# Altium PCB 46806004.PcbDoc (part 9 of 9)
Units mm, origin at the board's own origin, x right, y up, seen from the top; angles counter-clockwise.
Board outline 130 x 105 mm, 8 copper layers (Top Layer, P1-GND, L1-Signal, L2-Signal, L3-Signal, L4-Signal, P2-GND, Bottom Layer), stack 1.63 mm thick; 796 components, 496 nets, 2808 pads, 1195 vias.
Unrouted connection lines stored in the file: 1.
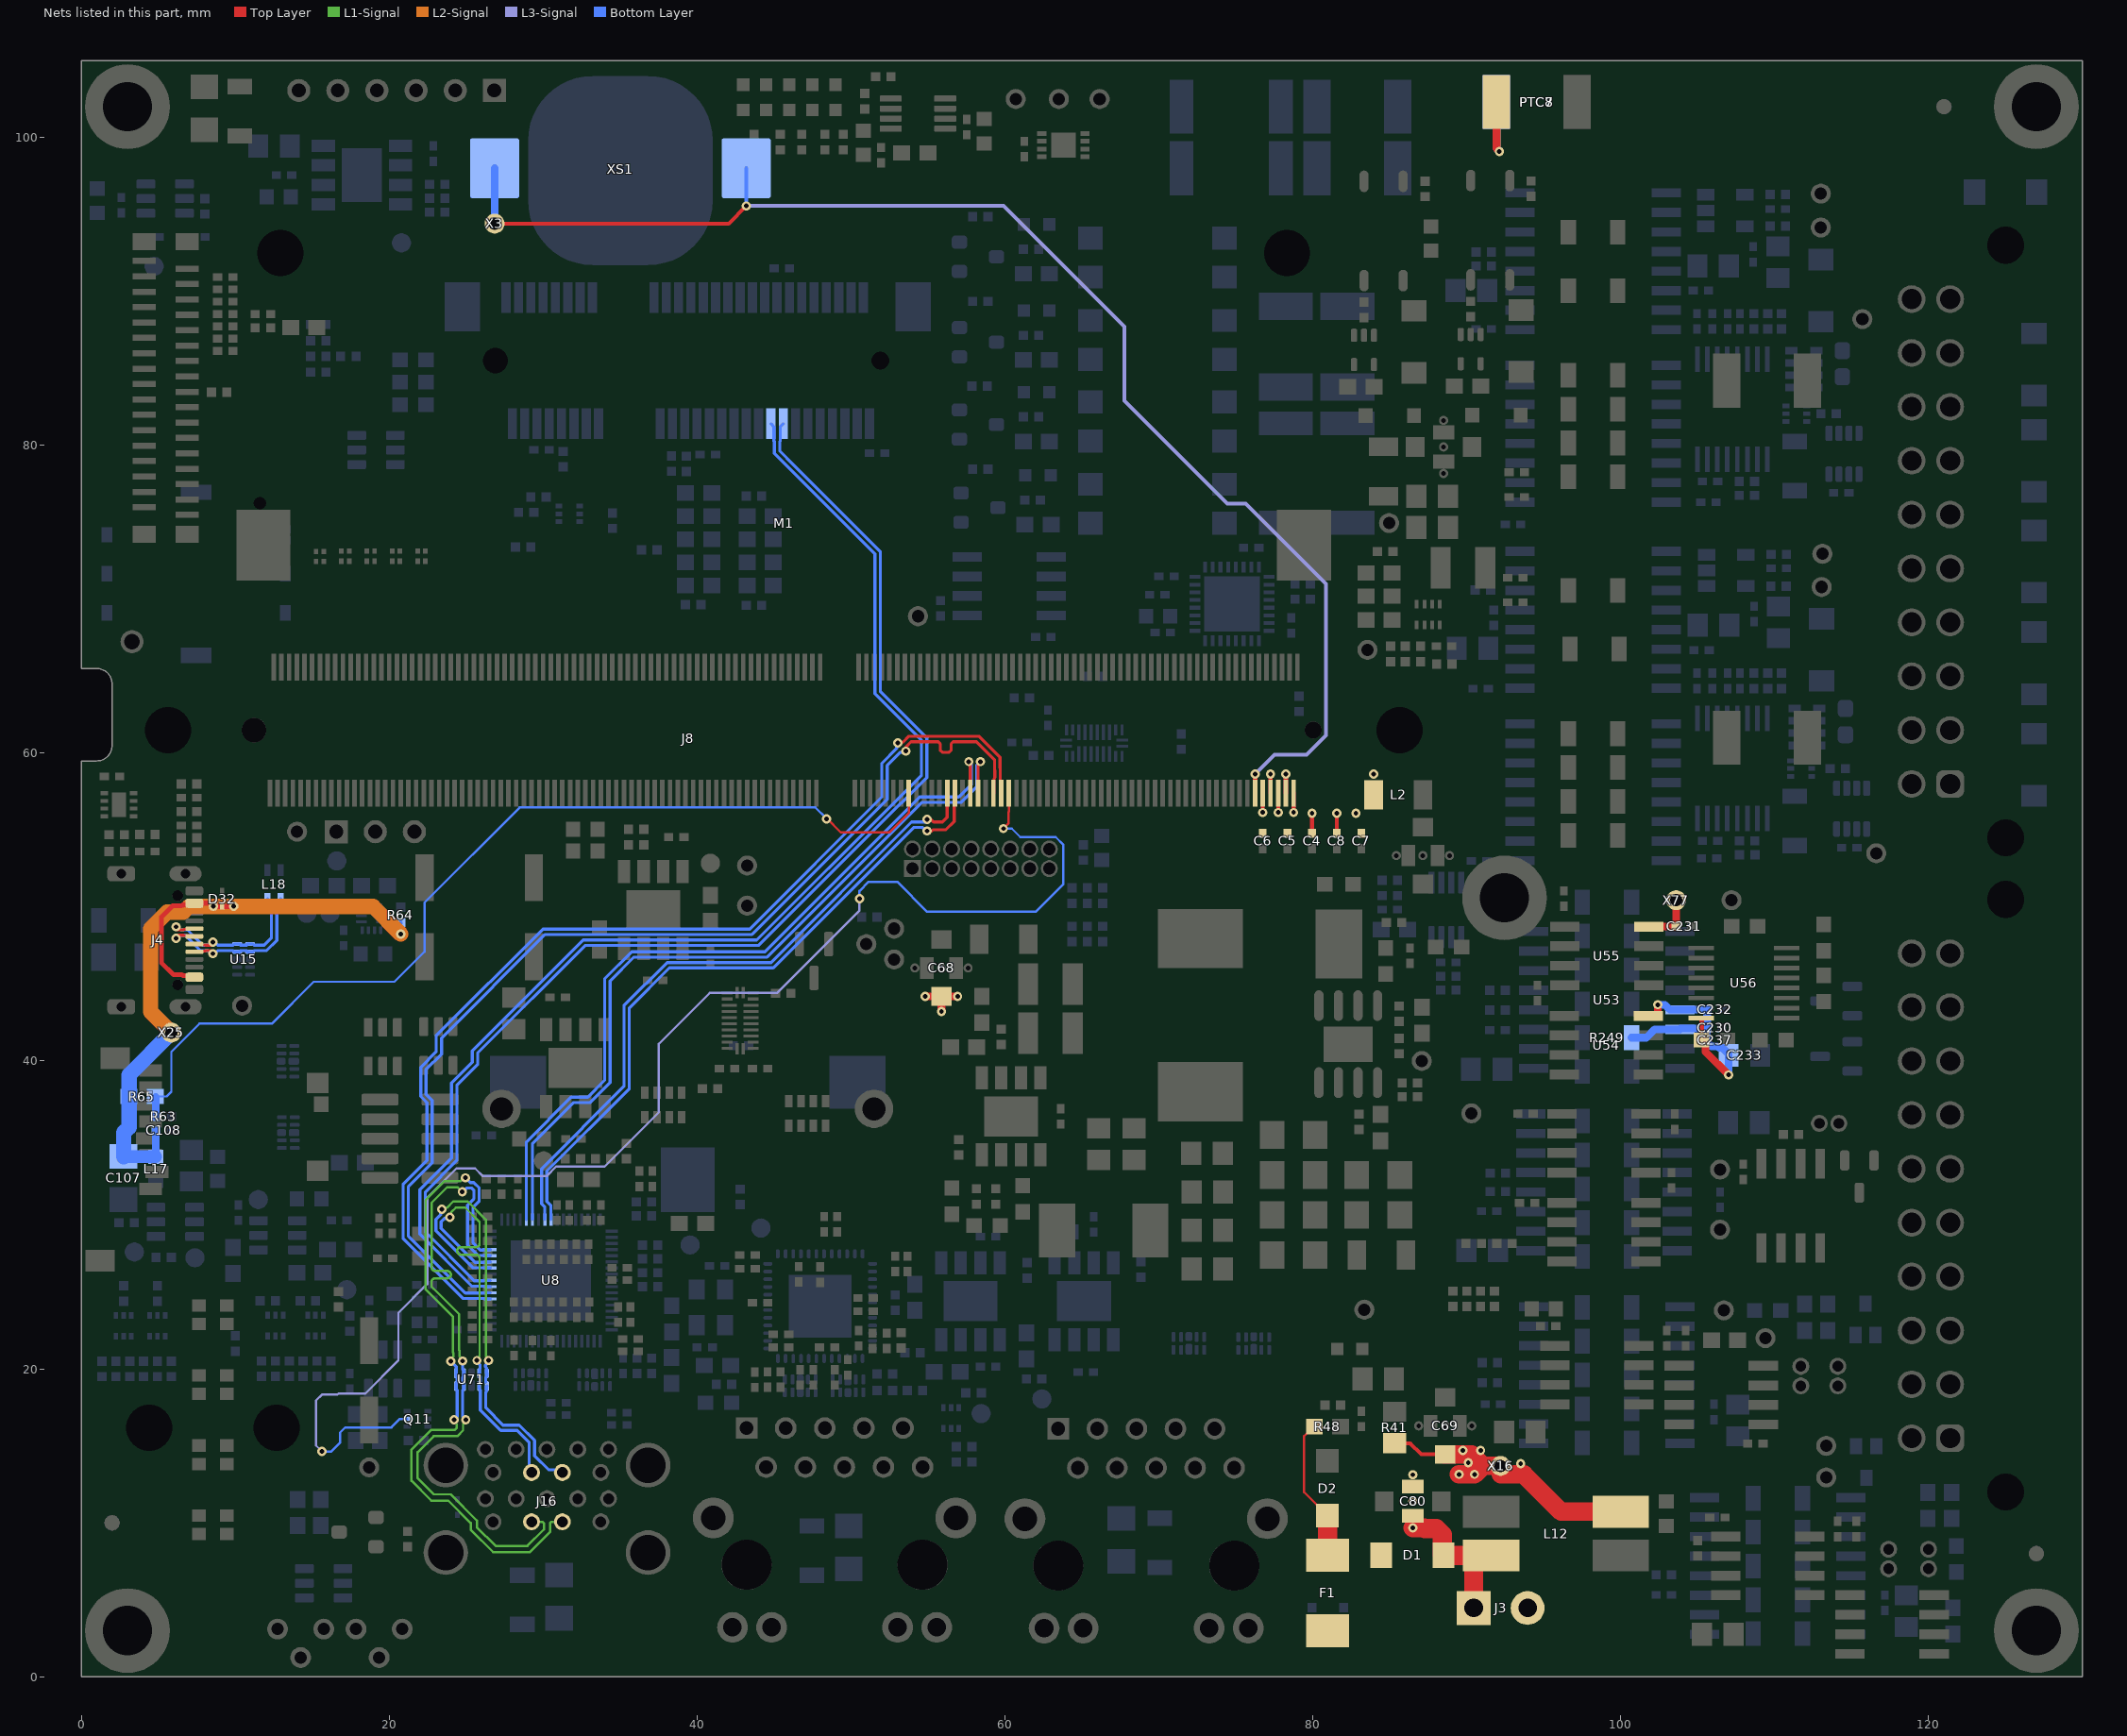
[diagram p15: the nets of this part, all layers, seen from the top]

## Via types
v1: diameter 0.6, hole 0.3, Top Layer to Bottom Layer, tented both sides, 1130 vias
v2: diameter 0.6, hole 0.3, Top Layer to Bottom Layer, 53 vias
v3: diameter 0.3, hole 0.3, Top Layer to Bottom Layer, 12 vias

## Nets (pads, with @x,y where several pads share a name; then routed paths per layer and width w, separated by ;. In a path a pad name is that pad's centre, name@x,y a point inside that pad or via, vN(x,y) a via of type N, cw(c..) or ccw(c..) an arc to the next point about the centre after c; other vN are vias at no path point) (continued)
USB1_VBUS: M1.159 R63.2 R65.2 | length 64
  Top Layer w0.15: v1(48.405,55.722) 48.422,55.722 48.45,55.75 49.35,54.85 52.5,54.85 53.75,56.1 M1.159@53.75,57.4
  Bottom Layer w0.15: R65.2@4.85,37.65 R65.2@4.8,37.7 5.55,37.7 5.85,38 5.85,40.6 7.675,42.425 12.375,42.425 15.1,45.15 20.341,45.15 22.3,47.109 22.3,50.299 28.476,56.475 34.408,56.475 35.092,56.475 47.694,56.475 48.405,55.764 v1(48.405,55.722)
  Bottom Layer w0.5: R63.2@4.85,36.4 R65.2@4.85,37.65
USB2_EN: M1.185 Q11.2 | length 92.5
  Top Layer w0.15: v1(59.9,55.1) 60.225,55.425 60.225,56.167 60.25,56.192 M1.185@60.25,57.4
  L3-Signal w0.15: v1(15.638,14.638) 15.25,15.026 15.25,17.942 15.633,18.325 16.633,18.325 16.708,18.4 18.45,18.4 20.6,20.55 20.6,23.642 22.475,25.517 22.475,31.125 24.371,33.021 25.586,33.021 26.083,32.525 30.225,32.525 30.85,33.15 34.001,33.15 37.522,36.671 37.522,41.122 40.825,44.425 45.187,44.425 50.55,49.788 v1(50.55,50.55)
  Bottom Layer w0.15: v1(15.638,14.638) 16.238,14.638 16.8,15.2 16.8,15.85 17.15,16.2 20.15,16.2 20.7,16.75 Q11.2@21.175,16.75 ; v1(50.55,50.55) 50.55,51.05 51.15,51.65 53,51.65 54.95,49.7 62,49.7 63.8,51.5 63.8,54.05 63.3,54.55 61,54.55 60.45,55.1 v1(59.9,55.1)
USB2_N: M1.181 U8.58 | length 70.1
  Top Layer w0.2: v1(53.566,60.134) 53.566,60.416 53.9,60.75 54.849,60.75 55.657,60.75 55.798,60.608 55.798,60.199 55.94,60.057 56.365,60.057 56.506,60.199 56.506,60.608 56.648,60.75 58.155,60.75 59.325,59.58 59.325,58.903 59.35,58.878 59.35,58.422 59.3,58.372 59.3,57.45 M1.181@59.25,57.4
  Bottom Layer w0.2: U8.58@26.564,24.947 26.262,24.947 26.237,24.922 24.948,24.922 21.25,28.621 21.25,31.85 22.8,33.4 22.8,37.445 22.4,37.845 22.4,39.45 23.4,40.45 23.4,41.488 30.132,48.22 43.57,48.22 52.35,57 52.35,59.2 53.207,60.057 53.49,60.057 v1(53.566,60.134)
USB2_P: M1.183 U8.57 | length 70.7
  Top Layer w0.2: v1(53.036,60.664) 53.07,60.697 53.353,60.697 53.755,61.1 58.3,61.1 59.675,59.725 59.675,59.048 59.7,59.023 59.7,58.399 59.7,57.45 M1.183@59.75,57.4
  Bottom Layer w0.2: U8.57@26.564,24.547 26.262,24.547 26.237,24.572 24.803,24.572 20.9,28.476 20.9,31.995 22.45,33.545 22.45,37.3 22.255,37.495 22.05,37.7 22.05,39.595 23.05,40.595 23.05,41.633 29.987,48.57 37.405,48.57 42.927,48.57 43.425,48.57 52,57.145 52,59.345 52.96,60.305 52.96,60.587 v1(53.036,60.664)
USB_1_N: J4.A7 J4.B7 L18.4 U15.5 U15.6 | length 12.6
  Top Layer w0.2: v1(6.15,48.725) 6.15,48.642 6.267,48.525 6.626,48.525 6.651,48.55 7.3,48.55 J4.B7@7.35,48.6 ; J4.A7@7.35,47.6 7.4,47.55 8.049,47.55 8.074,47.525 8.433,47.525 8.55,47.642 v1(8.55,47.725)
  Bottom Layer w0.2: v1(6.15,48.725) 6.258,48.725 6.458,48.525 6.895,48.525 7.895,47.525 8.242,47.525 8.442,47.725 v1(8.55,47.725) 8.658,47.725 8.858,47.525 9.183,47.525 9.866,47.525 9.941,47.6 U15.5@10.128,47.6 10.316,47.6 10.341,47.575 10.341,47.534 10.35,47.525 10.741,47.525 10.75,47.534 10.75,47.575 10.775,47.6 U15.6@10.962,47.6 11.15,47.6 11.225,47.525 11.889,47.525 12.35,47.986 12.35,50.158 12.233,50.275 12.2,50.275 12.1,50.375 L18.4@12.1,50.55
USB_1_P: J4.A6 J4.B6 L18.1 U15.4 U15.7 | length 13.2
  Top Layer w0.2: v1(6.15,47.975) 6.15,48.058 6.267,48.175 6.626,48.175 6.651,48.15 7.3,48.15 J4.A6@7.35,48.1 ; J4.B6@7.35,47.1 7.4,47.15 8.049,47.15 8.074,47.175 8.433,47.175 8.55,47.058 v1(8.55,46.975)
  Bottom Layer w0.2: v1(6.15,47.975) 6.258,47.975 6.458,48.175 6.75,48.175 7.75,47.175 8.242,47.175 8.442,46.975 v1(8.55,46.975) 8.658,46.975 8.858,47.175 9.328,47.175 9.866,47.175 9.941,47.1 U15.4@10.128,47.1 10.316,47.1 10.341,47.125 10.341,47.166 10.35,47.175 10.741,47.175 10.75,47.166 10.75,47.125 10.775,47.1 U15.7@10.962,47.1 11.15,47.1 11.225,47.175 12.034,47.175 12.7,47.841 12.7,50.158 12.817,50.275 12.85,50.275 12.95,50.375 L18.1@12.95,50.55
USB_1_VBUS: C107.2 C108.2 D32.1 J4.A4/B9 J4.B4/A9 L17.2 R64.1 R65.1 X25.1 | length 49.5
  Top Layer w0.3: J4.B4/A9@7.35,45.45 7.261,45.539 6.615,45.539 6.544,45.61 5.99,45.61 5.2,46.4 5.2,49.35 5.94,50.09 6.544,50.09 6.615,50.161 7.261,50.161 J4.A4/B9@7.35,50.25
  Top Layer w0.35: J4.A4/B9@7.35,50.25 8.38,50.25 8.593,50.037 D32.1@9.15,50.037 9.157,50.043 9.893,50.043 v1(9.9,50.05)
  L2-Signal w1: X25.1@5.85,41.85 4.5,43.2 4.5,48.6 5.575,49.675 6.624,49.675 6.999,50.05 v1(9.9,50.05) 18.953,50.05 v1(20.75,48.253)
  Bottom Layer w0.25: v1(20.75,48.253) R64.1@20.75,49
  Bottom Layer w0.5: C107.2@2.75,33.8 C107.2@2.76,33.79 ; L17.2@4.85,33.79 C108.2@4.85,35.5
  Bottom Layer w0.8: C107.2@2.76,33.79 L17.2@4.85,33.79
  Bottom Layer w1: C107.2@2.75,33.8 2.75,35.35 3.1,35.7 R65.1@3.1,37.7 3.1,39.1 X25.1@5.85,41.85
  other v1: 8.587,50.057
USB_2_SSRX_N: M1.175 U8.5 | length 51.1
  Top Layer w0.2: v1(57.65,59.45) 57.75,59.35 M1.175@57.75,57.4
  Bottom Layer w0.2: U8.5@28.911,29.695 28.911,34.745 31.817,37.65 32.9,37.65 34,38.75 34,45.345 35.755,47.1 44.405,47.1 54.455,57.15 57,57.15 57.829,57.979 57.829,59.271 v1(57.65,59.45)
USB_2_SSRX_P: M1.177 U8.6 | length 51.1
  Top Layer w0.2: M1.177@58.25,57.4 58.25,59.3 v1(58.4,59.45)
  Bottom Layer w0.2: U8.6@29.311,29.695 29.311,34.65 31.962,37.3 33.045,37.3 34.35,38.605 34.35,45.2 35.9,46.75 44.55,46.75 54.6,56.8 57.145,56.8 58.179,57.834 58.179,59.229 v1(58.4,59.45)
USB_2_SSTX_N: M1.169 U8.8 | length 44.1
  Top Layer w0.2: v1(54.95,55.7) 54.95,55.65 55.24,55.65 55.365,55.525 55.95,55.525 56.25,55.825 56.25,56.525 M1.169@56.25,57.4
  Bottom Layer w0.2: U8.8@30.111,29.695 30.111,30.511 29.9,30.723 29.9,33 35.25,38.35 35.25,43.595 38.055,46.4 44.805,46.4 53.93,55.525 54.95,55.525 54.95,55.65 v1(54.95,55.7)
USB_2_SSTX_P: M1.171 U8.9 | length 44.3
  Top Layer w0.2: v1(54.95,54.95) 55.24,54.95 55.315,55.025 56.157,55.025 56.7,55.568 56.7,56.575 56.75,56.625 M1.171@56.75,57.4
  Bottom Layer w0.2: U8.9@30.511,29.695 30.511,30.606 30.25,30.868 30.25,32.855 35.6,38.205 35.6,43.45 38.2,46.05 44.95,46.05 54.075,55.175 54.647,55.175 54.722,55.1 54.85,55.1 54.95,55 v1(54.95,54.95)
USBH2_N: J16.U2 U8.63 U71.2 U71.9 | length 28.9
  L1-Signal w0.15: v1(23.95,29.85) 24.036,29.936 24.036,30.184 24.331,30.478 24.937,30.478 25.875,29.541 25.875,28.702 25.875,28.147 cw(c25.635,28.147) 25.635,27.907 24.658,27.907 ccw(c24.658,27.667) 24.418,27.667 ccw(c24.658,27.667) 24.658,27.426 25.635,27.426 cw(c25.635,27.186) 25.875,27.186 25.875,26.143 25.875,23.312 25.875,20.847 25.7,20.672 v1(25.7,20.55)
  Bottom Layer w0.2: v1(23.95,29.85) 23.873,29.773 23.591,29.773 23.383,29.566 23.383,29.117 25.578,26.922 26.237,26.922 26.262,26.947 U8.63@26.564,26.947 ; v1(25.7,20.55) 25.7,20.479 25.9,20.279 25.9,20.005 25.875,19.98 25.875,19.742 U71.9@25.85,19.717 25.85,19.529 25.875,19.504 25.916,19.504 25.925,19.496 U71.2@25.925,19.133 ; U71.2@25.85,18.883 25.85,18.695 25.925,18.621 25.925,17.325 27.25,16 28.305,16 29.1,15.205 29.1,13.419 J16.U2@29.25,13.269 J16.U2@29.4,13.419
USBH2_P: J16.U3 U8.62 U71.1 U71.10 | length 29.2
  L1-Signal w0.15: v1(23.42,30.38) 23.506,30.466 23.753,30.466 24.165,30.878 25.103,30.878 26.275,29.706 26.275,23.146 26.275,20.847 26.45,20.672 v1(26.45,20.55)
  Bottom Layer w0.2: v1(23.42,30.38) 23.343,30.304 23.343,30.021 23.033,29.711 23.033,28.972 25.433,26.572 26.237,26.572 26.262,26.547 U8.62@26.564,26.547 ; U71.1@26.275,19.133 26.275,19.454 26.35,19.529 U71.10@26.35,19.717 26.325,19.742 26.325,20.067 26.25,20.142 26.25,20.242 26.45,20.442 v1(26.45,20.55) ; U71.1@26.35,18.883 26.325,18.858 26.325,18.533 26.275,18.483 26.275,17.47 27.395,16.35 28.45,16.35 29.45,15.35 29.45,14.35 30.35,13.45 31.069,13.45 J16.U3@31.25,13.269
USBH3_N: J16.L2 U8.64 U71.4 U71.7 | length 44.2
  L1-Signal w0.15: v1(24.75,31.508) 24.734,31.508 24.438,31.805 23.77,31.805 22.75,30.784 22.75,27.149 22.75,26.603 ccw(c22.99,26.603) 22.99,26.363 23.769,26.363 cw(c23.769,26.123) 24.009,26.123 cw(c23.769,26.123) 23.769,25.883 22.99,25.883 ccw(c22.99,25.643) 22.75,25.643 22.75,25.35 22.892,25.208 24.55,23.55 24.55,21.223 24.582,21.191 24.582,20.818 24.764,20.636 v1(24.764,20.514) ; v1(24.975,16.7) 24.975,16.578 24.8,16.403 24.8,16.009 24.422,15.631 22.891,15.631 21.85,14.59 21.85,12.9 22.9,11.85 24,11.85 25.7,10.15 25.7,9.716 26.916,8.5 28.983,8.5 30.05,9.567 30.05,9.981 29.962,10.069 J16.L2@29.25,10.069
  Bottom Layer w0.2: v1(24.75,31.508) 24.818,31.508 25.068,31.757 25.35,31.757 25.5,31.607 25.5,31.045 25.1,30.645 25.1,28.047 25.555,27.592 25.775,27.372 26.237,27.372 26.262,27.347 U8.64@26.564,27.347 ; v1(24.764,20.514) 24.764,19.991 24.85,19.904 U71.7@24.85,19.717 24.85,19.529 24.775,19.454 24.775,19.104 24.784,19.096 24.825,19.096 24.85,19.071 U71.4@24.85,18.883 24.85,18.695 24.775,18.62 24.775,16.9 v1(24.975,16.7)
USBH3_P: J16.L3 U8.65 U71.5 U71.6 | length 44.1
  L1-Signal w0.15: v1(24,20.5) 24,20.622 24.182,20.804 24.182,21.025 24.15,21.057 24.15,23.384 22.35,25.184 22.35,30.95 23.605,32.205 24.637,32.205 24.847,32.415 v1(24.95,32.415) ; v1(24.225,16.7) 24.225,16.578 24.4,16.403 24.4,16.175 24.256,16.031 22.726,16.031 21.45,14.755 21.45,12.734 22.734,11.45 23.834,11.45 25.3,9.984 25.3,9.55 26.75,8.1 29.148,8.1 30.45,9.402 30.45,9.981 30.538,10.069 J16.L3@31.25,10.069
  Bottom Layer w0.2: v1(24,20.5) 24.35,20.15 U71.6@24.35,19.717 24.35,19.529 24.425,19.454 24.425,19.104 24.416,19.096 24.375,19.096 24.35,19.071 U71.5@24.35,18.883 24.35,18.695 24.425,18.62 24.425,16.9 v1(24.225,16.7) ; v1(24.95,32.415) 24.96,32.415 25.267,32.107 25.495,32.107 25.85,31.752 25.85,30.9 25.45,30.5 25.45,28.192 25.92,27.722 26.085,27.722 26.108,27.745 26.562,27.745 U8.65@26.564,27.747
USBHUB1.USBH1_N: J8.36 U8.59 | length 82.8
  Bottom Layer w0.2: U8.59@26.564,25.347 26.262,25.347 26.237,25.372 25.383,25.372 22,28.755 22,31.645 24.05,33.695 24.05,38.566 25.4,39.916 25.4,40.666 32.603,47.87 43.875,47.87 53.105,57.1 53.117,57.1 54.58,58.563 54.58,60.845 51.55,63.875 51.55,72.955 45.025,79.48 45.025,80.251 45,80.276 45,81.2 J8.36@44.8,81.4
USBHUB1.USBH1_P: J8.38 U8.60 | length 82.2
  Bottom Layer w0.2: U8.60@26.564,25.747 26.562,25.745 26.156,25.745 26.133,25.722 25.528,25.722 22.35,28.9 22.35,31.5 24.4,33.55 24.4,38.421 25.75,39.771 25.75,40.521 32.748,47.52 37.84,47.52 44.02,47.52 53.25,56.75 53.262,56.75 54.93,58.418 54.93,60.99 51.9,64.02 51.9,73.1 46.346,78.654 46.229,78.771 45.375,79.625 45.375,80.251 45.4,80.276 45.4,81.2 J8.38@45.6,81.4
V1: D2.1 F1.2 R48.2 | length 9.3
  Top Layer w0.15: R48.2@80.1,16.25 80.05,16.25 79.426,15.626 79.426,11.996 80.263,11.159 80.288,11.159 80.95,10.497 D2.1@80.95,10.472
  Top Layer w1.25: F1.2@80.95,7.9 D2.1@80.95,10.472
V+: D1.2 F1.1 J3.2
V-: C80.2 D1.1 J3.1 L12.2 | length 10.2
  Top Layer w1.25: C80.2@86.5,9.675 87.234,9.675 87.284,9.625 88.006,9.625 88.405,9.226 88.405,7.975 D1.1@88.48,7.9 ; D1.1@88.51,7.89 L12.2@91.1,7.89 ; J3.1@90.45,4.469 90.45,7.24 L12.2@91.1,7.89 ; L12.2@91.58,7.89 L12.2@91.1,7.89
VBAT: M1.249 X3.1 XS1.2 | length 90.2
  Top Layer w0.25: X3.1@26.85,94.4 33.75,94.4 42.05,94.4 v1(43.2,95.55)
  Top Layer w0.3: M1.249@76.25,57.4 v1(76.25,58.65)
  L3-Signal w0.25: v1(43.2,95.55) 59.9,95.55 67.75,87.7 67.75,82.9 74.45,76.2 75.65,76.2 80.85,71 80.85,61.158 79.592,59.9 77.5,59.9 v1(76.25,58.65)
  Bottom Layer w0.25: XS1.2@43.19,98 43.19,95.56 v1(43.2,95.55)
  Bottom Layer w0.5: X3.1@26.85,94.4 XS1.2@26.85,98
VCC_232: C230.1 C231.1 C232.1 C233.2 C237.2 R249.1 U53.13 U53.14 U54.8 U55.8 U56.16 X77.1 | length 22.9
  Top Layer w0.3: U56.16@105.225,42.793 105.25,42.768 C237.2@105.25,41.368
  Top Layer w0.5: U54.8@101.808,42.934 102.209,42.934 102.402,43.127 v1(102.402,43.659) ; U55.8@101.831,48.734 103.566,48.734 C231.1@103.6,48.768 X77.1@103.6,50.45 ; C237.2@105.25,41.368 105.275,41.368 105.5,41.143 105.5,40.6 v1(107,39.1)
  Bottom Layer w0.5: R249.1@100.7,41.518 101.661,41.518 102.206,42.063 U53.14@103.85,42.063 103.9,42.113 105.095,42.113 105.15,42.168 C230.1@105.6,42.168 ; v1(102.402,43.659) 102.879,43.659 103.025,43.513 103.025,43.508 103.2,43.333 U53.13@103.85,43.333 105.578,43.333 C232.1@105.613,43.368 105.613,42.181 C230.1@105.6,42.168 ; v1(107,39.1) C233.2@107,40.381 ; C233.2@107.013,40.368 107.013,40.468 106.613,40.868 106.402,40.868 106.32,40.95 105.893,40.95 105.6,41.243 C230.1@105.6,42.168
VIN: C68.1 C69.1 L12.4 PTC7.1 PTC8.1 R41.1 X16.1 | length 27.8
  Top Layer w0.25: R41.1@85.3,15.175 86.325,15.175 87.05,14.45 C69.1@88.6,14.45
  Top Layer w0.5: v1(54.825,44.2) C68.1@55.875,44.2 ; v1(55.875,43.225) C68.1@55.875,44.2 ; v1(56.925,44.2) C68.1@55.875,44.2 ; PTC7.1@91.934,102.3 91.934,99.293 92.117,99.11 v1(92.117,99.083)
  Top Layer w1.2: C69.1@88.6,14.45 90.3,14.45 91.05,13.7 ; v1(89.5,13.15) v1(90.5,13.15) 91.05,13.7 ; X16.1@92.2,13.15 93.7,13.15 96.13,10.72 L12.4@100.01,10.72 ; X16.1@92.2,13.7 91.05,13.7
  Bottom Layer w0.5: PTC8.1@91.934,102.3 91.934,99.293 92.117,99.11 v1(92.117,99.083)
  other v1: 93.5,13.85 90.1,13.9 89.75,14.7 90.9,14.7
VT: C4.2 C5.2 C6.2 C7.2 C8.2 L2.2 M1.251 M1.253 M1.255 M1.257 M1.259 | length 8.1
  Top Layer w0.25: v1(76.75,56.15) M1.251@76.75,57.4 ; v1(77.75,56.15) M1.255@77.75,57.4 ; v1(78.75,56.15) M1.259@78.75,57.4 ; 79.95,55.15 v1(79.95,56.094) ; 81.55,55.15 v1(81.55,56.094)
  Top Layer w0.3: M1.253@77.25,57.4 v1(77.25,58.65) ; M1.257@78.25,57.4 v1(78.25,58.65)
  other v1: 82.8,56.1 83.95,58.65
pads on no net: D5.2 D5.4 D19.2 FID1.1 FID2.1 FID3.1 FID4.1 FID5.1 FID6.1 H5.0 J1.2 J1.3 J1.6 J4. J4.A8 J4.B8 J5.21 J5.22 J6.19 J6.20 J6.21 J6.22 J7.0 J7.10 J8.3 J8.5 J8.7 J8.17 J8.19 J8.45 J8.47 J8.49 J8.51 J8.MH1 J8.MH2 J8.MH3 J8.MP1 J8.MP2 J9.CD J9.MH1 J9.MH2 J9.MP1 J9.MP2 J10.0 J10.10 J11.1 J11.2 J11.3 J11.7 J11.8 J13.7 J13.9 J15.31 J15.32 J15.33 J15.34 LP1.0 M1. M1.0 M1.1@12.925,92.504 M1.1@78.325,92.5 M1.15 M1.16 M1.38 M1.52 M1.61 M1.63 M1.67 M1.69 M1.73 M1.75 M1.79 M1.81 M1.85 M1.87 M1.88 M1.90 M1.91 M1.92 M1.94 M1.96 M1.99 M1.100 M1.101 M1.102 M1.104 M1.105 M1.106 M1.107 M1.108 M1.111 M1.112 M1.113 M1.114 M1.116 M1.117 M1.118 M1.119 M1.120 M1.121 M1.123 M1.124 M1.125 M1.126 M1.128 M1.130 M1.132 M1.136 M1.138 M1.140 M1.142 M1.143 M1.144 M1.148 M1.150 M1.151 M1.152 M1.153 M1.154 M1.156 M1.160 M1.162 M1.164 M1.166 M1.168 M1.172 M1.174 M1.176 M1.178 M1.180 M1.184 M1.186 M1.188 M1.190 M1.192 M1.248 M1.250 ME1.0 ME2.0 ME3.1 ME4.1 RA2.8 S1.3 S2.3 U3.3 U3.4 U3.5 U3.6 U3.7 U3.10 U3.11 U3.12 U3.13 U3.15 U3.25 U3.26 U3.27 U3.28 U3.29 U3.30 U3.31 U4.3 U4.4 U4.5 U5.9 U7.3 U8.11 U8.12 U8.14 U8.15 U8.25 U8.32 U8.33 U8.47 U8.48 U8.50 U8.51 U8.67 U8.68 U9.1 U9.5 U10.4 U10.8 U12.6 U13.5 U13.6 U13.7 U13.8 U16.9 U26.20 U26.21 U26.22 U26.23 U26.39 U26.40 U26.46 U29.1 U29.5 U30.1 U30.5 U32.1 U32.5 U35.4 U37.7 U37.8 U38.7 U38.8 U43.12 U45.12 U48.8 U48.9 U51.3 U60.1 U61.1 U64.4 U65.1 U65.5 U66.4 U66.5 U67.4 U67.5

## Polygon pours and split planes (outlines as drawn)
no net on M2 "NONET_L-01_P-001" (none): 21.227,28.573 21.227,31.927 23.5,34.2 25.2,34.2 27.1,36.1 27.1,43.8 26.2,44.7 24.9,44.7 23.7,45.9 23.7,47.6 22.8,48.5 19.2,48.5 17.6,46.9 10.7,46.9 9.519,45.719 0,45.719 0,90 125,90 125,36.616 121.984,36.616 119,39.6 102,39.6 99.1,42.5 81.837,42.5 68.737,29.4 50.2,29.4 47.1,26.3 23.5,26.3
5V on L4-Signal "5V_L06_P021" (solid, remove dead copper, pour order 21): 0,0 0,59.5 0,105 97.1,105 97.1,14.7 99.45,12.35 104.275,12.35 104.76,11.865 104.76,0.003 104.763,0
2V5 on L4-Signal "2V5_L06_P014" (solid, remove dead copper, pour order 14): 58.85,20.7 58.85,19 58.1,18.25 47.751,18.25 46.25,19.751 41.351,24.65 41.351,29.663 41.588,29.9 42.186,29.9 44.075,28.011 44.075,24.575 46.95,21.7 49.75,21.7 49.75,21.1 48.5,21.1 47.826,20.426 47.826,19.698 48.074,19.45 50.35,19.45 52.25,21.35 56.15,21.35 56.8,20.7
VIN on L4-Signal "VIN_L06" (solid, remove dead copper, pour order 20): 93.85,14.179 93.85,12.25 87.8,12.25 85.85,14.2 78.15,14.2 74.1,18.25 67.25,18.25 62.05,23.45 62.05,25.3 54.35,33 54.35,44.4 54.8,44.85 62.5,52.55 62.5,77.55 84.95,100 92.25,100 92.5,99.75 92.5,92.9 92.45,92.85 89.5,92.85 85.679,89.029 85.679,60.05 85.679,53.954 70.025,38.3 65.605,33.88 65.605,32.414 68.4,29.619 68.4,24.603 70.671,22.35 85.679,22.35
MPCI1_3V3 on L4-Signal "MPCI1_3V3_L06_P017" (solid, remove dead copper, pour order 17): 38.45,44.4 39.268,45.218 39.268,46.548 37.816,48 34.25,48 32.45,49.8 32.45,54.15 41.9,63.6 41.9,78.8 40.2,80.5 30.6,80.5 29.05,82.05 29.05,84.05 29.573,84.573 46.577,84.573 50,81.15 50,78.85 50.3,78.55 51.35,78.55 53.35,80.55 53.35,87.85 48.15,93.05 48.15,95.56 45.739,97.971 44.254,97.971 36.633,90.35 28.6,90.35 25.027,86.777 25.027,81.123 28.55,77.6 19.45,68.5 19.45,53.942 28.992,44.4
1V0_ETH on L4-Signal "1V0_ETH_L06_P016" (solid, remove dead copper, pour order 16): 66.1,19.15 62.75,22.5 56.9,22.5 54.2,25.2 52.5,25.2 49.1,28.6 45.022,28.6 44.075,27.653 44.075,27.153 44.579,26.65 48.675,26.65 51.488,23.838 51.488,22.487 49.7,20.7 48.4,20.7 48.4,20.699 47.826,20.126 47.826,19.698 48.074,19.45 50.35,19.45 52.25,21.35 56.15,21.35 56.8,20.7 60.5,20.7 62.788,18.412 65.862,18.412 66.1,18.65
MPCI1_1V5 on L4-Signal "MPCI1_1V5_L06_P019" (solid, remove dead copper, pour order 19): 37.1,53.587 37.8,52.887 38.782,52.887 45.625,59.73 45.625,74.475 50,78.85 50,81.15 46.577,84.573 29.573,84.573 29.05,84.05 29.05,82.05 30.6,80.5 40.2,80.5 41.9,78.8 41.9,63.6 37.1,58.8
GND on L4-Signal "GND_L06_P015" (solid, remove dead copper, pour order 15): 44.579,26.65 48.675,26.65 51.488,23.838 51.488,22.487 49.7,20.7 48.4,20.7 44.579,24.521
1V8C on Bottom Layer "NONET_L-01_P-001" (solid, pour order 6): 71.803,67.95 71.803,72.003 72.525,72.725 75.5,72.725 75.5,73.75 71.85,73.75 70.6,72.5 70.6,67.435 65.158,67.435 63.343,69.25 62.808,69.25 62.808,66.492 63.55,65.75 78.5,65.75 81,68.25 81,71.25 80.5,71.75 79.8,71.75 79.538,71.488 79.538,69.7 79.388,69.55 78.15,69.55 77.85,69.25 77.85,67.435 76.904,66.489 76.904,66.45 72.6,66.45 71.8,67.25 71.8,67.95
1V8_SW on Bottom Layer "1V8_SW_L08_P005" (solid, pour order 5): 2.462,87.164 2.727,87.428 7.156,87.428 10.555,87.428 17.327,94.2 22.7,94.2 23.125,94.625 23.125,97.05 21.975,98.2 21.975,99.646 21.984,99.646 22.438,100.1 23.95,100.1 25.038,99.012 25.038,92.888 23.35,91.2 17.4,91.2 14.307,88.107 14.307,84.607 13.9,84.2 4.55,84.2 2.465,86.285
+V5_SW on Bottom Layer "+V5_SW_L08_P000" (solid, remove dead copper, pour order 0): 2.452,89.148 2.45,87.85 2.65,87.65 7.372,87.65 7.65,87.928 8.5,87.928 8.85,88.278 8.85,91.778 7.1,93.528 4.5,93.528 4.5,89.9 3.946,89.346 2.65,89.346
VT on Bottom Layer "VT_L08_P025" (solid, remove dead copper, pour order 25): 75.75,54.4 75.75,58.1 77.35,59.7 84.05,59.7 85.087,58.663 85.087,54.737 84.5,54.15 76,54.15
GND on Top Layer "GND_L01_P034" (solid, pour order 34): 64.75,17.15 67.25,19.65 67.25,24.3 65.1,26.45 57.05,26.45 52.8,30.7 43.45,30.7 39.6,26.85 39.6,19.15 41.6,17.15 46.55,17.15
GND on Top Layer "GND_L01_P011" (solid, remove dead copper, pour order 11): 14.02,54.9 15.07,55.95 18.05,55.95 19.1,54.9 19.1,49.903 20.75,48.253 20.795,48.298 30.202,48.298 30.95,47.55 30.95,43.5 30.45,43 19.523,43 14.02,48.503
MPCI1_3V3 on Top Layer "MPCI1_3V3_L01_P018" (solid, remove dead copper, pour order 18): 32,56.25 21.85,56.25 19.45,53.85 19.45,51.038 20.086,50.403 31.253,50.403 31.5,50.65 32,51.15
+V5_SW on Top Layer "NONET_L-01_P-001" (solid, remove dead copper, pour order 3): 7.781,88.128 7.55,88.359 7.55,90.6 8.128,91.178 9.55,91.178 9.55,88.128
GND on Top Layer "GND_L01_P032" (solid, pour order 32): 84.85,29.1 84.85,34.228 84.8,34.278 83.9,34.278 83.9,35.378 85.928,35.378 87.343,36.793 87.343,38.893 88.231,39.782 89.4,39.782 89.653,39.528 89.653,30.403 88.35,29.1
5V on Top Layer "5V_L01_P022" (solid, remove dead copper, pour order 22): 86.5,52.1 87.8,52.1 88.75,52.1 91.6,49.25 91.6,44.707 91.193,44.3 89.02,44.3 88.6,44.72 88.6,47.875 87.475,47.875 86.5,48.85 86.5,50.9
GND on Top Layer "GND_L01_P035" (solid, remove dead copper, pour order 35): 97.4,8.92 102.4,8.92 102.4,2.65 97.4,2.65
GND on Top Layer "GND_L01_P033" (solid, pour order 33): 27.85,24.05 27.85,26.6 28.65,27.4 33.9,27.4 34.15,27.15 34.15,24.6 33.6,24.05
V+ on Top Layer "V+_L01_P031" (solid, pour order 31): 83.465,8.735 85.135,8.735 85.17,8.7 85.17,6.301 85.171,6.3 83.636,6.3 83.45,6.486
V- on Top Layer "V-_L01_P030" (solid, pour order 30): 85.8,9.687 85.8,9.06 90.391,4.469 91.59,4.469 91.59,8.92 89.51,8.92 88.174,10.256 86.369,10.256
NetC80_1 on Top Layer "NETC80_1_L01_P029" (solid, pour order 29): 80.213,12.6 83.05,12.6 83.05,10.75 85.25,10.75 85.25,13.15 83.3,15.1 80.35,15.1 80.213,14.963
VIN on Top Layer "VIN_L01_P028" (solid, pour order 28): 100.01,11.76 98.18,11.76 94.89,15.05 87.95,15.05 87.95,13.85 89.45,12.35 93.35,12.35 96.02,9.68 100.01,9.68
3V3 on Top Layer "3V3_L01_P010" (solid, remove dead copper, pour order 10): 90.972,68.95 90.548,69.374 90.548,78.848 91.15,79.45 92.7,79.45 93.15,79 93.15,69.405 92.695,68.95
VT on Top Layer "VT_L01_P004" (solid, remove dead copper, pour order 4): 75.75,54.4 75.75,58.1 77.35,59.7 84.05,59.7 85.087,58.663 85.087,54.737 84.5,54.15 76,54.15
5V on Top Layer "5V_L01_P009" (solid, remove dead copper, pour order 9): 75.456,38.2 69.228,38.2 69.228,34.225 65.35,34.225 64.4,33.275 64.4,31.75 65.35,30.8 65.35,26.969 68.468,23.85 71.8,23.85 73.3,25.35 73.3,34.2 74.4,35.3 75.456,35.3
NetC85_1 on Top Layer "NETC85_1_L01_P001" (solid, remove dead copper, pour order 1): 80.6,47.777 80.6,43.393 79.157,43.393 79.075,43.475 79.075,47.775
AVDD33 on Top Layer "AVDD33_L01_P026" (solid, remove dead copper, pour order 26): 26.1,22.45 26.65,22.45 27.7,23.5 27.7,27.45 28.85,28.6 28.85,29.3 28,30.15 25.9,30.15 25.9,22.45
NetC70_2 on Top Layer "NETC70_2_L01_P008" (solid, remove dead copper, pour order 8): 84.25,26.05 83.5,25.3 79.5,25.3 78.75,26.05 78.75,36.6 80.05,37.9 82.15,37.9 82.7,37.35 82.7,36.639 84.25,35.089
3V3 on L2-Signal "3V3_L04_P024" (solid, remove dead copper, pour order 24): 0,0 0,105 70.888,105 70.888,89.112 73.4,86.6 93.353,86.6 96.95,83.003 96.95,52.168 98,51.118 98,13.8 99.45,12.35 99.45,0
DVDD12 on L2-Signal "DVDD12_L04_P023" (solid, remove dead copper, pour order 23): 28.823,29.2 32.25,29.2 34,27.45 34,23.25 33.05,22.3 27.95,22.3 27.6,22.65 27.6,27.977 28.492,28.869
NetC257_2 on L2-Signal "NETC257_2_L04_P013" (solid, remove dead copper, pour order 13): 21.537,7.279 21.537,14.276 23.11,15.85 37.5,15.85 38.9,14.45 38.9,7.4 37.6,6.1 22.716,6.1
1V8 on L3-Signal "1V8_L05_P012" (solid, remove dead copper, pour order 12): 0,0 0,105 70.888,105 70.888,89.112 73.4,86.6 86.5,86.6 86.5,90.95 87.553,92.003 87.897,92.003 88.9,91 88.9,86.6 96.95,78.55 96.95,52.168 98,51.118 98,13.8 99.45,12.35 99.45,0
GND on L1-Signal "GND_L03_P027" (solid, remove dead copper, pour order 27): 0,0 0,105 70.888,105 70.888,89.112 73.4,86.6 93.353,86.6 96.95,83.003 96.95,52.168 98,51.118 98,13.8 99.45,12.35 99.45,0
SHLD on P1-GND (split plane): 1.423,6 1.432,5.951 1.46,5.91 1.501,5.882 1.55,5.873 3,5.873 3.009,5.874 3.226,5.866 3.45,5.839 3.671,5.795 3.888,5.734 4.1,5.656 4.305,5.561 4.502,5.451 4.69,5.326 4.867,5.186 5.033,5.033 5.186,4.867 5.326,4.69 5.451,4.502 5.561,4.305 5.656,4.1 5.734,3.888 5.795,3.671 5.839,3.45 5.866,3.226 5.874,3.009 5.873,3 5.873,0.51 0.51,0.51 0.51,58.99 1,58.99 1.002,58.99 1.169,58.999 1.336,59.027 1.423,59.052
SHLD on P1-GND (split plane): 129.49,0.51 124.127,0.51 124.127,3 124.126,3.009 124.134,3.226 124.161,3.45 124.205,3.671 124.266,3.888 124.344,4.1 124.439,4.305 124.549,4.502 124.674,4.69 124.814,4.867 124.967,5.033 125.133,5.186 125.31,5.326 125.498,5.451 125.695,5.561 125.9,5.656 126.112,5.734 126.329,5.795 126.55,5.839 126.774,5.866 126.991,5.874 127,5.873 128.45,5.873 128.499,5.882 128.54,5.91 128.568,5.951 128.577,6 128.577,99 128.568,99.049 128.54,99.09 128.499,99.118 128.45,99.127 127,99.127 126.991,99.126 126.774,99.134 126.55,99.161 126.329,99.205 126.112,99.266 125.9,99.344 125.695,99.439 125.498,99.549 125.31,99.674 125.133,99.814 124.967,99.967 124.814,100.133 124.674,100.31 124.549,100.498 124.439,100.695 124.344,100.9 124.266,101.112 124.205,101.329 124.161,101.55 124.134,101.774 124.126,101.991 124.127,102 124.127,103.45 124.118,103.499 124.09,103.54 124.049,103.568 124,103.577 6,103.577 5.951,103.568 5.91,103.54 5.882,103.499 5.873,103.45 5.873,102 5.874,101.991 5.866,101.774 5.839,101.55 5.795,101.329 5.734,101.112 5.656,100.9 5.561,100.695 5.451,100.498 5.326,100.31 5.186,100.133 5.033,99.967 4.867,99.814 4.69,99.674 4.502,99.549 4.305,99.439 4.1,99.344 3.888,99.266 3.671,99.205 3.45,99.161 3.226,99.134 3.009,99.126 3,99.127 1.55,99.127 1.501,99.118 1.46,99.09 1.432,99.049 1.423,99 1.423,65.948 1.336,65.973 1.169,66.001 1.002,66.01 1,66.01 0.51,66.01 0.51,104.49 129.49,104.49
GND_AIN2 on P1-GND (split plane): 119.2,91.2 121.95,91.2 122.3,90.85 122.3,89.127 121.773,88.6 117.9,88.6 116.25,86.95 116.25,75.7 99.3,75.7 99.3,94.653 101.65,97.003 113.397,97.003
GND_AIN1 on P1-GND (split plane): 116.25,60.15 117.5,58.9 122.036,58.9 122.3,58.636 122.3,52.718 100.445,52.718 100.2,52.963 99.3,53.863 99.3,73.408 103.9,73.408 104.455,73.963 116.25,73.963
GND on P1-GND (split plane): 157 vertices, not listed, extent 1.677,0.51 128.323,103.323
GND_CAN2 on P1-GND (split plane): 122.3,21.6 117.9,21.6 114.2,17.9 112.006,17.9 110.468,16.362 110.468,14.468 110,14 100.6,14 100.2,14.4 100.2,24.8 116.427,24.8 118.527,26.9 122.3,26.9
GND_CAN1 on P1-GND (split plane): 122.3,0.51 111.3,0.51 111.3,12.673 112.1,13.473 112.1,15.7 112.696,16.296 114.923,16.296 118.527,19.9 122.3,19.9
GND on P1-GND (split plane): 122.3,46.1 118.527,46.1 117.994,46.633 117.994,51.118 122.3,51.118
GND_485 on P1-GND (split plane): 117.5,33.9 122.3,33.9 122.3,28.524 117.524,28.524 115.5,26.5 100.2,26.5 100.2,36.918 114.482,36.918
GND_232 on P1-GND (split plane): 116.4,51.115 116.4,45.9 117.9,44.4 122.3,44.4 122.3,35.6 118.527,35.6 115.609,38.518 100.2,38.518 100.2,51.118 116.9,51.118
GND on P2-GND (split plane): 123.873,103.323 123.873,102 123.882,101.755 123.911,101.511 123.959,101.27 124.026,101.034 124.111,100.803 124.213,100.58 124.333,100.366 124.47,100.162 124.622,99.969 124.789,99.789 124.969,99.622 125.162,99.47 125.366,99.333 125.58,99.213 125.803,99.111 126.034,99.026 126.27,98.959 126.511,98.911 126.755,98.882 127,98.873 128.323,98.873 128.323,6.127 127,6.127 126.755,6.118 126.511,6.089 126.27,6.041 126.034,5.974 125.803,5.889 125.58,5.787 125.366,5.667 125.162,5.53 124.969,5.378 124.789,5.211 124.622,5.031 124.47,4.838 124.333,4.634 124.213,4.42 124.111,4.197 124.026,3.966 123.959,3.73 123.95,3.685 123.95,19.9 123.95,21.6 123.95,26.9 123.95,28.524 123.95,33.9 123.95,35.6 123.95,44.4 123.95,46.1 123.95,51.118 123.95,52.718 123.95,59.3 122.65,60.6 118.527,60.6 118,61.127 118,86.373 118.527,86.9 122.8,86.9 123.75,87.85 123.75,91.929 122.779,92.9 120,92.9 114.2,98.7 100.5,98.7 97.1,95.3 97.1,52.018 98,51.118 98,13.8 99.45,12.35 109.1,12.35 109.1,0.51 6.127,0.51 6.127,3 6.118,3.245 6.089,3.489 6.041,3.73 5.974,3.966 5.889,4.197 5.787,4.42 5.667,4.634 5.53,4.838 5.378,5.031 5.211,5.211 5.031,5.378 4.838,5.53 4.634,5.667 4.42,5.787 4.197,5.889 3.966,5.974 3.73,6.041 3.489,6.089 3.245,6.118 3,6.127 1.677,6.127 1.677,57.147 4.09,59.56 4.118,59.601 4.127,59.65 4.127,65.489 4.118,65.538 4.09,65.579 1.677,67.992 1.677,98.873 3,98.873 3.245,98.882 3.489,98.911 3.73,98.959 3.966,99.026 4.197,99.111 4.42,99.213 4.634,99.333 4.838,99.47 5.031,99.622 5.211,99.789 5.378,99.969 5.53,100.162 5.667,100.366 5.787,100.58 5.889,100.803 5.974,101.034 6.041,101.27 6.089,101.511 6.118,101.755 6.127,102 6.127,103.323
SHLD on P2-GND (split plane): 180 vertices, not listed, extent 0.51,0.51 129.49,104.49
+V5_SW on P2-GND (split plane): 9.073,52.097 9.073,49.503 8.647,49.077 7.6,49.077 7.551,49.068 7.51,49.04 7.047,48.577 5.803,48.577 5.377,49.003 5.377,51.497 6.553,52.673 8.497,52.673
3V2_AIN1 on P2-GND (split plane): 116.25,60.15 117.5,58.9 122.036,58.9 122.3,58.636 122.3,52.718 100.445,52.718 100.2,52.963 99.3,53.863 99.3,73.408 103.9,73.408 104.455,73.963 116.25,73.963
3V2_AIN2 on P2-GND (split plane): 119.2,91.2 121.95,91.2 122.3,90.85 122.3,89.127 121.773,88.6 117.9,88.6 116.25,86.95 116.25,75.7 99.3,75.7 99.3,94.653 101.65,97.003 113.397,97.003
5V_CAN2 on P2-GND (split plane): 122.3,21.6 117.9,21.6 114.2,17.9 112,17.9 110.468,16.368 110.467,14.467 110,14 100.6,14 100.2,14.4 100.2,24.8 116.427,24.8 118.527,26.9 122.3,26.9
5V_CAN1 on P2-GND (split plane): 122.3,0.51 111.3,0.51 111.3,12.673 112.1,13.473 112.1,15.7 112.7,16.3 114.927,16.3 118.527,19.9 122.3,19.9
GND on P2-GND (split plane): 122.3,46.1 118.527,46.1 117.994,46.633 117.994,51.118 122.3,51.118
5V_485 on P2-GND (split plane): 117.5,33.9 122.3,33.9 122.3,28.524 117.524,28.524 115.5,26.5 100.2,26.5 100.2,36.918 114.482,36.918
VCC_232 on P2-GND (split plane): 116.4,51.115 116.4,45.9 117.9,44.4 122.3,44.4 122.3,35.6 118.527,35.6 115.609,38.518 100.2,38.518 100.2,51.118 116.9,51.118

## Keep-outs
Bottom Layer:
  region: 118.9,60.6 118.527,60.6 118,61.127 118,86.373 118.527,86.9 122.8,86.9 123.75,87.85 123.75,91.929 122.779,92.9 121.95,92.9 121.95,91.2 122.3,90.85 122.3,89.127 121.773,88.6 117.9,88.6 116.25,86.95 116.25,60.15 117.5,58.9 118.9,58.9
  region: 118.9,60.6 118.9,58.9 122.036,58.9 122.3,58.636 122.3,0 123.95,0 123.95,59.3 122.65,60.6
  region: 121.95,92.9 120,92.9 118,94.9 114.2,98.7 100.5,98.7 97.1,95.3 97.1,94.653 99.3,94.653 101.65,97.003 113.397,97.003 116.4,94 119.2,91.2 121.95,91.2
  region: 99.3,75.7 116.25,75.7 116.25,73.963 116.037,73.963 104.455,73.963 99.3,73.963
  region: 117.994,51.124 118,51.118 118,46.627 118.527,46.1 123.95,46.1 123.95,44.4 117.88,44.4 116.4,45.88 116.4,51.115
  region: 118,52.718 123.95,52.718 123.95,51.118 118,51.118
  region: 100.2,26.5 115.5,26.5 117.6,28.6 123.95,28.6 123.95,26.9 118.527,26.9 116.427,24.8 100.2,24.8
  region: 100.2,38.518 115.609,38.518 118.527,35.6 123.95,35.6 123.95,33.9 117.5,33.9 114.482,36.918 100.2,36.918
  region: 110.909,12.281 112.1,13.473 112.1,15.7 112.3,15.9 114.527,15.9 118.527,19.9 123.95,19.9 123.95,21.6 118.4,21.6 114.3,17.5 111.6,17.5 110.468,16.367 110.468,14.467 109.595,13.595
  region: 100.2,52.963 100.613,52.55 104.5,52.55 104.5,52.718 118,52.718 118,51.118 100.2,51.118
  region: 109.1,0 109.1,12.35 99.45,12.35 98,13.8 98,51.118 97.1,52.018 97.1,94.653 99.3,94.653 99.3,53.863 100.2,52.963 100.2,14.4 100.6,14 110,14 111.3,12.7 111.3,0
Keep-Out Layer:
  the board outline again, w0.05

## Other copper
Top Layer:
  region net NetC85_1: 75.456,49.887 75.862,49.481 79.809,49.481 80.176,49.848 81.7,49.848 81.7,45.352 79.744,45.352 78.846,46.25 75.679,46.25 75.456,46.026 72.7,46.026 72.7,49.887
  region net NetC58_2: 31.866,42.05 31.866,43.316 32.3,43.75 33.15,43.75 34.14,44.74 34.14,47.56 33.16,47.56 33.16,45.56 32.6,45 31.75,45 31.064,44.314 31.064,42.05
  region net NetC82_2: 62.225,32.827 61.904,33.148 61.904,34.653 63.053,34.653 63.85,33.855 63.85,31.475 64.575,30.75 64.575,29 62.235,29 62.225,28.99
  region net NetC68_3: 57.725,46.95 57.375,47.3 55.225,47.3 55.225,48.5 55.575,48.85 58.925,48.85 58.925,46.95
  region net NetC73_2: 62.15,40.45 62.816,40.45 62.818,40.452 62.818,48.818 62.9,48.9 60.682,48.9 60.4,48.618 60.4,41.07 61.035,40.435
  region net GND: 63.75,46.35 65.65,46.35 66.05,45.95 66.05,40.9 65.6,40.45 63.75,40.45
  region net GND: 69.15,34.975 69.15,36.465 68.49,37.125 66.01,37.125 65.35,36.465 65.35,34.975
  region net GND: 9.45,85.878 9.45,91.5 9.828,91.5 10.15,91.178 10.15,90.95 10.75,90.35 10.75,90.05 10.75,86.05 10.578,85.878
  region net GND: 76,54.1 89.75,54.1 90.05,53.8 90.05,52.8 89.8,52.55 85.537,52.55 85.118,52.969 84.319,52.969 83.45,52.1 83.45,50.75 82.95,50.25 77.4,50.25 75.75,51.9 75.75,53.85
  region net 1V8: 51.15,21.625 52.575,21.625 52.575,20.728 52.112,20.265 51.402,20.265 51.15,20.517 51.15,21.025
  region net 1V0_ETH: 48,29.2 49.35,29.2 49.35,28.02 49.215,27.885 48,27.885
  region net 1V0_ETH: 43.475,27.653 44.647,27.653 44.977,27.323 44.977,26.594 44.636,26.253 43.475,26.253
  region net 1V0_ETH: 51.15,24.85 52.236,24.85 52.405,24.681 52.405,23.919 51.986,23.5 51.15,23.5
  region net 1V8: 52.624,26.618 53.924,26.618 53.924,26.018 53.16,25.253 52.875,25.253 52.624,25.504 52.624,26.018
  region net GND: 46.45,19.25 49.5,19.25 49.55,19.3 49.55,19.9 50.05,19.9 50.35,19.6 50.35,17.55 49.95,17.15 46.55,17.15 46.15,17.55 46.15,18.95
  region net GND: 43.5,19.1 45.671,19.1 45.674,19.103 45.674,18.503 45.149,17.979 43.75,17.979 43.5,18.229 43.5,18.5
  region net 1V8: 43.5,19.5 43.5,20.1 43.982,20.582 45.196,20.582 45.674,20.103 45.674,19.503
  region net DVDD12: 31.35,28.4 31.839,28.889 32.498,28.889 32.987,28.4 33.2,28.4 33.2,27.8 31.35,27.8
  region net DVDD12: 28.9,28.5 29.273,28.873 29.284,28.861 30.289,28.861 30.75,28.4 30.75,27.8 28.9,27.8
  region net AVDD12: 29.45,23.35 29.45,23.05 29.061,22.661 29.061,22.15 29.561,22.15 29.95,22.539 29.95,23.35
  region net DVDD12: 31.95,23.65 31.95,23.05 32.2,23.05 32.2,22.75 32.5,22.45 33.1,22.45 33.1,22.9 33.25,23.05 33.25,23.65
  region net DVDD12: 31.55,23.65 31.55,23.05 31.3,23.05 31.3,23 30.906,22.606 30.511,22.606 30.511,22.789 30.25,23.05 30.25,23.65
  region net DVDD12: 28.9,23 28.497,22.597 28.109,22.597 27.85,22.856 27.85,23.65 28.9,23.65
  region net GND: 73.525,25.75 73.5,25.775 73.5,34.75 75.2,34.75 76.55,36.1 78.15,36.1 78.15,26.5 77.4,25.75
  region net NetC69_3: 87.2,28.35 87.6,27.95 87.6,23.45 89.5,21.55 89.5,17.55 87.95,17.55 86.8,18.7 86.8,20.6 84.95,22.45 84.95,28.35
  region net NetC80_3: 88.35,12.05 91.3,12.05 91.59,11.76 91.59,9.68 89.76,9.68 88.35,11.09
  region net V1: 82.35,11.85 82.35,7.9 79.55,7.9 79.55,11.85
  region net GND: 25.7,30.15 24.95,30.15 22.927,28.127 22.927,22.123 24.046,21.004 25.304,21.004 25.7,21.4
  region net GND: 27.05,20.9 27.3,21.15 29.561,21.15 31.025,21.15 31.025,19.4 29.525,17.9 29,17.9 26.95,19.95 26.95,20.8
  pour cut-out: 3.331,92.678 7.554,92.678 7.554,74.778 3.331,74.778
  region net V+: 83.48,8.72 83.45,8.75 83.45,6.486 82.35,5.386 82.35,4.1 79.55,1.9 79.55,0.55 82.15,0.55 84.182,2.582 84.182,8.72
  region net V+: 93.05,5.85 94.85,5.85 95.45,5.25 95.45,1.9 94.1,0.55 87.2,0.55 84.9,2.85 84.9,8.7 85.17,8.7 86.85,7.02 86.85,4.1 88.25,2.7 91.75,2.7 92.5,3.45 92.5,5.3
  pour cut-out: 84.5,72.8 84.5,74.25 86.2,74.25 86.2,72.8
  pour cut-out: 59.1,34.653 59.1,29.45 56.7,29.45 56.7,34.652
  pour cut-out: 36.129,53.053 39.471,53.053 39.471,51.548 36.129,51.548
  pour cut-out: 34.859,48.053 39.471,48.053 39.471,46.548 34.859,46.548
  pour cut-out: 96.415,61.276 95.863,61.276 95.863,55.328 96.415,55.328
  pour cut-out: 96.415,84.114 95.863,84.114 95.863,78.903 96.415,78.903
  pour cut-out: 44.984,81.318 44.984,81.957 41.47,81.957 41.47,81.318
  pour cut-out: 69.95,69.8 69.95,72.187 66.175,72.187 66.175,69.8
  pour cut-out: 55.025,98.384 55.025,98.919 53.275,98.919 53.275,98.368
  pour cut-out: 2.925,54.398 2.925,53.863 4.675,53.863 4.675,54.415
  pour cut-out: 24.386,33.3 21.988,33.3 21.988,32.79 24.386,32.79
  pour cut-out: 24.467,35.297 24.467,37.143 21.95,37.143 21.95,35.297
  pour cut-out: 20.75,37.224 20.75,32.676 18.2,32.676 18.2,37.224
  pour cut-out: 53.45,42.425 59.2,42.425 59.2,49.35 53.45,49.35
  pour cut-out: 88.948,73.396 90.548,73.396 90.548,70.696 88.948,70.696
  region net GND: 86.25,69.246 88.496,69.246 88.642,69.392 88.642,70.143 88.999,70.5 90.1,70.5 90.5,70.1 90.5,68.3 89.9,67.7 88.876,67.7 88.65,67.926 88.65,68.65 88.5,68.8 86.3,68.8 86.25,68.85
  text "Ivy Rev. 1.0" at 71.6,99.954 h1.7
  text "46806004" at 71.6,98.304 h1.7
L1-Signal:
  pour cut-out: 58.755,37.605 63.305,37.605 68.35,42.65 68.35,48.896 63.1,48.896 61.094,46.89 61.094,41.094 58.786,38.786 58.786,37.636
  pour cut-out: 30.55,58.2 28.1,55.75 26.15,55.75 25.4,56.5 25.4,58.904 24.643,59.661 18.361,59.661 17.125,60.897 17.15,67.937 15.5,69.3 15.5,70.92 17.13,70.92 23.968,70.92 26.95,67.937 26.9,67.887 26.9,58.85 27.55,58.2
  pour cut-out: 46.75,34.031 46.75,30.769 47.219,30.3 50.6,30.3 50.6,33.108 49.677,34.031
  pour cut-out: 58.35,35.11 62.292,35.11 62.301,35.101 62.301,33.801 60.56,32.06 58.71,32.06 58.35,32.419
L2-Signal:
  pour cut-out: 69.472,59.073 70.908,60.51 70.908,62.217 68.868,64.258 67.726,64.258 67.726,60.757 67.709,60.74 69.376,59.073
L3-Signal:
  pour cut-out: 57.3,60 57.36,59.94 58.91,59.94 64.1,54.75 63.685,54.335 57.375,54.335
  pour cut-out: 67.5,56.75 72.7,56.75 72.7,56.353 72.1,55.753 72.1,52.8 67.275,47.975 65.192,47.975 65.192,50.167 65.275,50.25 66.2,50.25 67.25,51.3
  pour cut-out: 27,75.271 32.205,75.271 46.849,60.627 53.212,60.627 53.212,58.202 51.61,56.6 49.35,56.6 30.895,75.055 27,75.055
Bottom Layer:
  region net GND: 7.9,34.225 7.9,36.1 7.25,36.75 6.5,36.75 6.35,36.6 6.35,34.925 7.05,34.225
  region net 5V: 8.735,33.875 8.075,34.535 8.075,35.125 8.15,35.2 9.35,35.2 9.45,35.1 9.45,34.36 8.965,33.875
  region net NetC104_2: 6.755,30.718 6.4,31.073 6.4,32.825 7.9,32.825 8.055,32.67 9.34,32.67 9.34,31.75 8.998,31.75 7.965,30.718
  region net NetL17_1: 4.245,30.718 4.36,30.833 4.36,32.21 5.34,32.21 5.34,30.832 5.455,30.718
  pour cut-out: 22.624,42.35 25.391,42.35 25.4,42.359 25.4,41.983 22.762,41.983 22.624,42.121
  pour cut-out: 42.703,24.428 42.705,24.43 43.5,24.43 43.5,23.77 43.358,23.628 42.703,23.628
  pour cut-out: 38.85,24.44 38.841,24.431 38.841,20.2 37.4,20.2 37.4,24.65 38.85,24.65
  pour cut-out: 15.864,21.915 15.864,21.315 17.014,21.315 17.014,21.915
  pour cut-out: 97.65,16.6 97.65,16 98.125,16 98.125,16.6
  pour cut-out: 96.85,21 96.85,20.4 98,20.4 98,21
  pour cut-out: 96.85,28.7 96.85,28.1 98,28.1 98,28.7
  pour cut-out: 96.85,33.1 96.85,32.5 98,32.5 98,33.1
  pour cut-out: 97.65,40.718 97.65,34.7 98.125,34.7 98.125,40.718
  pour cut-out: 96.85,47.318 96.85,46.718 98,46.718 98,47.318
  pour cut-out: 96.85,49.518 96.85,48.918 98,48.918 98,49.518
  pour cut-out: 96.85,23.2 96.85,22.6 98,22.6 98,23.2
  pour cut-out: 22.75,95.8 21.723,95.8 21.478,96.046 21.478,99.856 21.572,99.95 22.75,99.95
  pour cut-out: 15.2,88.15 17.15,88.15 17.15,84.45 15.2,84.45
  pour cut-out: 42.7,76.4 45.65,76.4 45.65,69.9 42.7,69.9
  pour cut-out: 7.31,93.403 7.31,97.4 8.35,97.4 8.35,93.403
  pour cut-out: 19.275,84.555 20.39,84.555 20.39,83.6 19.275,83.6
  pour cut-out: 84.3,73.9 84.3,84.674 73,84.674 73,73.9
  pour cut-out: 55.309,27.802 60.221,27.802 60.221,25.997 55.309,25.997
  pour cut-out: 34.459,27.747 33.483,27.747 33.115,27.379 33.115,26.115 33.483,25.747 34.459,25.747
  pour cut-out: 45.25,20.675 44.6,21.325 44.6,26.825 45.25,27.475 47.515,27.475 50.75,27.475 51.4,26.825 51.4,21.325 50.75,20.675
P1-GND (plane layer: these items are gaps in the copper):
  region: 111.3,0 111.3,12.7 110,14 100.6,14 100.2,14.4 100.2,52.963 99.3,53.863 99.3,94.653 101.65,97.003 113.397,97.003 119.2,91.2 121.95,91.2 121.95,92.9 120,92.9 114.2,98.7 100.5,98.7 97.1,95.3 97.1,52.018 98,51.118 98,13.8 99.45,12.35 109.1,12.35 109.1,0
  region: 123.95,35.6 118.527,35.6 115.609,38.518 100.2,38.518 100.2,36.918 114.482,36.918 117.5,33.9 123.95,33.9
  region: 123.95,21.6 117.9,21.6 114.2,17.9 112.006,17.9 110.468,16.362 110.468,14.468 109.595,13.595 110.909,12.281 112.1,13.473 112.1,15.7 112.696,16.296 114.923,16.296 118.527,19.9 123.95,19.9
  region: 123.95,28.524 117.524,28.524 115.5,26.5 100.2,26.5 100.2,24.8 116.427,24.8 118.527,26.9 123.95,26.9
  region: 118,75.7 118,73.963 104.455,73.963 103.9,73.408 97.1,73.408 97.1,75.7
  region: 121.95,92.9 122.779,92.9 123.75,91.929 123.75,87.85 122.8,86.9 118.527,86.9 118,86.373 118,61.127 118.527,60.6 122.65,60.6 123.95,59.3 123.95,0 122.3,0 122.3,58.636 122.036,58.9 117.5,58.9 116.25,60.15 116.25,86.95 117.9,88.6 121.773,88.6 122.3,89.127 122.3,90.85 121.95,91.2
  region: 117.994,51.124 117.994,46.633 118.527,46.1 123.95,46.1 123.95,44.4 117.9,44.4 116.4,45.9 116.4,51.115
  region: 123.95,52.718 123.95,51.118 100.2,51.118 100.2,52.963 100.445,52.718
  lines w0.25: 6,0 6,3 ccw(c3,3) 3,6 1.55,6 1.55,99 3,99 ccw(c3,102) 6,102 ; 124,0 124,3 cw(c127,3) 127,6 128.45,6 128.45,99 127,99 cw(c127,102) 124,102 124,103.45 6,103.45 6,102 ; 6,102 6,102
P2-GND (plane layer: these items are gaps in the copper):
  region: 121.95,92.9 122.779,92.9 123.75,91.929 123.75,87.85 122.8,86.9 118.527,86.9 118,86.373 118,61.127 118.527,60.6 122.65,60.6 123.95,59.3 123.95,0 122.3,0 122.3,58.636 122.036,58.9 117.5,58.9 116.25,60.15 116.25,86.95 117.9,88.6 121.773,88.6 122.3,89.127 122.3,90.85 121.95,91.2
  region: 116.4,75.7 116.4,73.963 104.455,73.963 103.9,73.408 99.1,73.408 99.1,75.7
  region: 123.95,52.718 123.95,51.118 100.2,51.118 100.2,52.963 100.445,52.718
  region: 117.994,51.124 117.994,46.633 118.527,46.1 123.95,46.1 123.95,44.4 117.9,44.4 116.4,45.9 116.4,51.115
  region: 123.95,35.6 118.527,35.6 115.609,38.518 100.2,38.518 100.2,36.918 114.482,36.918 117.5,33.9 123.95,33.9
  region: 123.95,28.524 117.524,28.524 115.5,26.5 100.2,26.5 100.2,24.8 116.427,24.8 118.527,26.9 123.95,26.9
  region: 123.95,21.6 117.9,21.6 114.2,17.9 112,17.9 110.468,16.368 110.467,14.467 109.595,13.595 110.909,12.281 112.1,13.473 112.1,15.7 112.7,16.3 114.927,16.3 118.527,19.9 123.95,19.9
  region: 111.3,0 111.3,12.7 110,14 100.6,14 100.2,14.4 100.2,52.963 99.3,53.863 99.3,94.653 101.65,97.003 113.397,97.003 119.2,91.2 121.95,91.2 121.95,92.9 120,92.9 114.2,98.7 100.5,98.7 97.1,95.3 97.1,52.018 98,51.118 98,13.8 99.45,12.35 109.1,12.35 109.1,0
  lines w0.25: 6,0 6,3 ccw(c3,3) 3,6 1.55,6 1.55,57.2 4,59.65 4,65.489 1.55,67.939 1.55,99 3,99 ccw(c3,102) 6,102 ; 124,0 124,3 cw(c127,3) 127,6 128.45,6 128.45,99 127,99 cw(c127,102) 124,102 124,103.45 6,103.45 6,102 ; 6,102 6,102 ; 5.25,48.95 5.25,51.55 6.5,52.8 8.55,52.8 9.2,52.15 9.2,49.45 8.7,48.95 7.6,48.95 7.1,48.45 5.75,48.45 5.25,48.95
Multi-Layer:
  pour cut-out: 118.527,80.15 130,80.15 130,60.85 118.527,60.85 118,61.377 118,79.623

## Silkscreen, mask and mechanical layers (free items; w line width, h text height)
Top Overlay:
  circle w0.15: c102.35,4.65 r1.063
  text "CONTACTS" at 2.2,80.68 h1.3 r90
  text "Verdin System-on-Module" at 31.865,74.82 h2.5
  text "DSI" at 3.9,70 h1.3
  text "EXT" at 71.2,55.7 h1.3 r270
  text "USB OTG" at 9.75,44.15 h1.3 r90
  text "SD CARD" at 10.25,41 h1.3
  text "RS485 TERM" at 111.4,37.35 h1.3
  text "JTAG" at 17.65,33.4 h1.3 r90
  text "MAIN" at 4.475,23.13 h1
  text "CAN2 TERM" at 112.15,21.8 h1.3
  text "PWR_EN" at 3.056,18.818 h1
  text "ETH2" at 51.5,18.05 h1.3
  text "ETH1" at 71.75,18.05 h1.3
  text "USB3.0" at 32.4,16.5 h1.3
  text "CAN1 TERM" at 121.45,6.25 h1.3
  text "RESET" at 12,5.4 h1.3
  text "REC" at 17.603,5.4 h1.3
  text "+" at 101.678,3.703 h3
  text "PWR" at 101.25,0.3 h1.3
Bottom Overlay:
  lines w0.15: 3.15,18.7 4.95,18.7 6.2,17.45 6.2,14.446 6.446,14.2 9.1,14.2 ; 7.95,17.45 11.349,17.45 12.614,18.715 14.414,18.715 ; 87.21,30.8 87.21,36.4 ; 87.21,34.745 91.955,34.745 ; 87.35,17.75 87.35,23.35 ; 87.35,21.695 92.094,21.695 ; 98.4,5.9 98.4,11.1 ; 98.4,8.5 103.5,8.5 ; 105.46,47.6 108.65,47.6 ; 108.64,44.813 108.64,50.413
  text ".DocumentNumber" at 78.383,31.91 h2.5
Top Solder:
  text "Ivy Rev. 1.0" at 71.6,99.954 h1.7
  text "46806004" at 71.6,98.304 h1.7
M1:
  circle w0.05: c127,102 r2.9
  circle w0.05: c3,3 r1.6
  circle w0.05: c127,3 r1.6
  circle w0.05: c127,3 r2.9
  circle w0.05: c3,3 r2.9
  circle w0.05: c127,102 r1.6
  circle w0.05: c3,102 r1.6
  circle w0.05: c3,102 r2.9
  lines w0.05: 0,15 0,105 125,105 ; 3.2,79.7 8.2,79.7 ; 5,0 130,0 130,90
M2:
  lines w0.05: 0,45.719 0,90 125,90 125,36.616 121.984,36.616 119,39.6 102,39.6 99.1,42.5 81.837,42.5 68.737,29.4 50.2,29.4 47.1,26.3 41.1,26.3 23.5,26.3 21.227,28.573 21.227,31.927 23.5,34.2 25.2,34.2 27.1,36.1 27.1,43.8 26.2,44.7 24.9,44.7 23.7,45.9 23.7,47.6 22.8,48.5 19.2,48.5 17.6,46.9 10.7,46.9 9.519,45.719 0,45.719
50R - TOP:
  drawing of 153 lines, arcs and shapes, not listed
50R - L1-Signal:
  drawing of 225 lines, arcs and shapes, not listed
50R - BOT:
  drawing of 209 lines, arcs and shapes, not listed
50R - L2-Signal:
  drawing of 151 lines, arcs and shapes, not listed
90R - TOP:
  drawing of 482 lines, arcs and shapes, not listed
90R - L1-Signal:
  drawing of 260 lines, arcs and shapes, not listed
90R - BOT:
  drawing of 694 lines, arcs and shapes, not listed
95R - TOP:
  lines w0.18: 70.25,57.4 70.31,57.46 70.31,58.367 70.335,58.392 70.335,60.035 72.55,62.25 74.967,62.25 75.63,61.587 75.63,60.86 75.64,60.85 75.64,60.165 75.85,59.955 75.85,59.85 ; 70.6,53.4 70.6,53.505 70.81,53.715 70.81,54.107 71.109,54.405 73.589,54.405 75.335,56.152 75.335,56.408 75.31,56.433 75.31,57.34 75.25,57.4 ; 70.75,57.4 70.69,57.46 70.69,58.367 70.665,58.392 70.665,59.898 72.687,61.92 74.83,61.92 75.3,61.45 75.3,60.723 75.31,60.713 75.31,60.165 75.1,59.955 75.1,59.85 ; 71.25,55.05 71.355,55.05 71.565,55.26 73.525,55.26 74.165,55.9 74.165,56.408 74.19,56.433 74.19,57.34 74.25,57.4 ; 71.25,55.8 71.355,55.8 71.565,55.59 73.388,55.59 73.835,56.037 73.835,56.408 73.81,56.433 73.81,57.34 73.75,57.4 ; 71.35,53.4 71.35,53.505 71.14,53.715 71.14,53.97 71.245,54.075 73.725,54.075 75.665,56.015 75.665,56.408 75.69,56.433 75.69,57.34 75.75,57.4 ; 71.75,57.4 71.81,57.46 71.81,58.367 71.835,58.392 71.835,60.052 72.413,60.63 73.53,60.63 73.739,60.839 73.714,60.863 73.714,61.013 73.634,61.093 ; 72.25,57.4 72.19,57.46 72.19,58.367 72.165,58.392 72.165,59.915 72.55,60.3 73.667,60.3 74.384,61.017 74.384,61.093
95R - BOT:
  drawing of 408 lines, arcs and shapes, not listed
